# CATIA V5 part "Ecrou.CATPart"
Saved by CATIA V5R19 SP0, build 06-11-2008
Part number: Ecrou
Publications: "H", "L", "La", "rvis"
Bounding box of the stored display mesh (mm): x -40 to 0, y 0 to 30, z 0 to 38
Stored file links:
  G:\EU_thinkMotion\CFAO_2010\MMS_groupe3\MMS_groupe3\A reprendre\evulliez\evulliez\Ecrou.CATPart
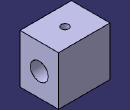
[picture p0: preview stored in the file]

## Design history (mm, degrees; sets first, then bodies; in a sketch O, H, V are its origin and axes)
Parameters
  H = 38 mm
  L = 40 mm
  La = 30 mm
  rvis = 7 mm
  Lr = 10 mm
Body1 (main body)
  Sketch1 on zx-plane, origin (0, 0, 0), H (-1, 0, 0), V (0, 0, 1)
    line L1 (0, 0) -> (40, 0)
    line L2 (40, 0) -> (40, 38)
    line L3 (40, 38) -> (0, 38)
    line L4 (0, 38) -> (0, 0)
    length L3 = 40 {= L}
    length L2 = 38 {= H}
    horizontal: L1 H, L3 H
    vertical: L2 V, L4 V
  Pad1: profile Sketch1, direction (0, 1, 0), length 30 {= La}
  Point1: type OnPlane, Support face of Pad1 from Sketch1.L4, H 15 {= La /2}, V 18 {= H -20mm}, Direction (0, 1, 0)
  Sketch2 on face of Pad1 from Sketch1.L4, origin (0, 25, 25), H (0, 1, 0), V (0, 0, 1)
    point P1 (-10, -7)
    reference projected point E1 (-10, -7) from Point1
    coincidence: E1 P1
  Hole1: placed by Sketch2, at (0, 15, 18) direction (-1, 0, 0), diameter 14 {= 2*rvis}, through (limit type 6)
  Point2: type OnPlane, Support face of Pad1 from Sketch1.L3, H -20 {= -L /2}, V 15 {= La /2}, Direction (1, 0, 0)
  Sketch3 on face of Pad1 from Sketch1.L3, origin (-40, 25, 38), H (1, 0, 0), V (0, 1, 0)
    point P1 (20, -10)
    reference projected point E1 (20, -10) from Point2
    coincidence: E1 P1
  Hole2: placed by Sketch3, at (-20, 15, 38) direction (0, 0, -1), diameter 6, depth 8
